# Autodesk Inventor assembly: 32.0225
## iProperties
Created: 2012-10
Part Number: 32.0225
Document SubType Name: Assembly
Designer: Administrator
Description: CABLE TROLLEY CIRCULAR LINES
Stock Number: 32.0225 CABLE TROLLEY CIRCULAR LINES
Author: Administrator
